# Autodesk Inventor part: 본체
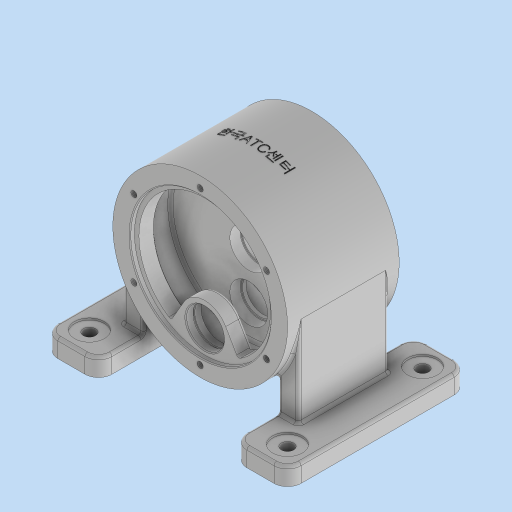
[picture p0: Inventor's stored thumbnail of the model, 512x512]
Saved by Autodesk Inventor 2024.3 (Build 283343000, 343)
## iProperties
Created: 2025-12
Part Number: 본체
Material: 일반
Document SubType Name: Modeling
Designer: PC2-02
Density: 1 g/cm^3
Appearance: 기본값
Author: PC2-02
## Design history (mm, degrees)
sketch "스케치1"
  geometry: L1 (-135, 100)-(135, 100); L2 (135, 100)-(135, -100); L3 (135, -100)-(-135, -100); L4 (-135, -100)-(-135, 100); 1 further point
  constraints: 8 end point, 2 parallel, 1 horizontal, 1 perpendicular
  dimensions: "d0" = 270 distance between parallel lines of L2 L4; "d1" = 135 distance from line of point (0, 0) L4; "d2" = 200 distance between parallel lines of L3 L1; "d3" = 100 distance from line of L3 point (0, 0)
extrude "돌출1" new body sketch "스케치1" distance "d4" = 20; taper "d5" = 0 deg
sketch "스케치2"
  geometry: L1 (135, 0)-(-135, 0) reference; C1 r 97 at (0, 120); 2 further points
  constraints: 1 centre point, 1 midpoint, 1 vertical alignment
  dimensions: "d6" = 194 diameter of C1; "d7" = 120 distance from line of L1 C1.centre
extrude "돌출2" join sketch "스케치2" stored distance "d8" = 124; taper "d9" = 0 deg
sketch "스케치3"
  geometry: L1 (0, 20)-(270, 20) reference; L2 (0, 0)-(270, 0) reference; L3 (60, 20)-(210, 20); L4 (210, 20)-(210, 0); L5 (210, 0)-(60, 0); L6 (60, 0)-(60, 20); L7 (0, 0)-(0, 20) reference; L8 (270, 0)-(270, 20) reference; 3 further points
  constraints: 8 end point, 2 parallel, 2 point on line, 1 horizontal, 1 perpendicular
  dimensions: "d10" = 60 distance between parallel lines of L7 L6; "d11" = 60 distance between parallel lines of L8 L4
extrude "돌출3" cut sketch "스케치3" extent not by distance; stored distance "d12" = 0; taper "d13" = 0 deg
sketch "스케치4"
  geometry: L1 (75, 50)-(97, 50); L2 (97, 50)-(97, -50); L3 (97, -50)-(75, -50); L4 (75, -100)-(75, 100) reference; L5 (75, -50)-(75, 50); L6 (-75, 100)-(-75, -100) reference; L7 (-75, 50)-(-97, 50); L8 (-97, 50)-(-97, -50); L9 (-97, -50)-(-75, -50); L10 (-75, -50)-(-75, 50); 2 further points
  constraints: 16 end point, 3 parallel, 3 point on line, 2 horizontal, 2 perpendicular, 1 collinear
  dimensions: "d14" = 100 distance between parallel lines of L3 L1; "d15" = 50 distance from line of L3 point (0, 0); "d16" = 22 distance between parallel lines of L2 L4; "d17" = 100 distance between parallel lines of L9 L7; "d18" = 50 distance from line of point (0, 0) L7; "d19" = 22 distance between parallel lines of L6 L8
extrude "돌출4" join sketch "스케치4" stored distance "d20" = 10; taper "d21" = 0 deg
sketch "스케치5"
  geometry: L1 (75, 20)-(75, 0) reference; L2 (75, 8)-(36.6, 30.17); L3 (75, 20)-(75, 58.486) reference; L4 (75, 0)-(135, 0) reference; L5 (-36.6, 30.17)-(-75, 8); L6 (-135, 0)-(-75, 0) reference; L7 (-75, 20)-(-75, 58.486) reference; L8 (-75, 0)-(-75, 20) reference; A1 r 97 centre (0, 120) between (36.6, 30.17) and (75, 58.486) reference; 2 further points
  constraints: 4 end point, 2 point on circle, 2 point on line
  dimensions: "d22" = 60 deg angle of L2 L3; "d23" = 8 distance from line of L4 L2.start; "d24" = 8 distance from line of L6 L5.end; "d25" = 60 deg angle of L7 L5
extrude "돌출5" join sketch "스케치5" stored distance "d26" = 12; taper "d27" = 0 deg
sketch "스케치6"
  geometry: C1 r 97 at (0, 0) reference; 2 further points
  constraints: 1 coincident
hole "구멍1" sketch "스케치6" at (0, 0) diameter "d28" = 146; stored, may be unused: countersink angle "d32" = 90 deg, drill point angle "d34" = 0 deg; dims "d29" = 6, "d30" = 156, "d31" = 5, "d33" = 17
sketch "스케치7"
  geometry: C1 r 97 at (0, 0) reference; 2 further points
  constraints: 1 coincident
hole "구멍2" sketch "스케치7" at (0, 0) diameter "d35" = 42; stored, may be unused: countersink angle "d39" = 90 deg, drill point angle "d41" = 0 deg; dims "d36" = 6, "d37" = 174, "d38" = 32, "d40" = 12
sketch "스케치8"
  geometry: C1 r 97 at (0, 0) reference; 2 further points
  constraints: 1 coincident
hole "구멍3" sketch "스케치8" at (0, 0) diameter "d42" = 146; stored, may be unused: countersink angle "d46" = 90 deg, drill point angle "d48" = 0 deg; dims "d43" = 6, "d44" = 156, "d45" = 5, "d47" = 17
sketch "스케치9"
  geometry: C1 r 97 at (0, 0) reference; 2 further points
  constraints: 1 coincident
hole "구멍4" sketch "스케치9" at (0, 0) diameter "d49" = 174; stored, may be unused: countersink angle "d53" = 90 deg, drill point angle "d55" = 0 deg; dims "d50" = 6, "d51" = 4, "d52" = 2, "d54" = 32
sketch "스케치10"
  geometry: L1 (23.383, -39)-(37.148, -62.842); L2 (-23.383, -39)-(-37.148, -62.842); L3 (0, 0)-(0, -73); C1 r 21 at (0, 0) reference; C2 r 97 at (0, 0) reference; A1 r 27 centre (0, -52.5) between (23.383, -39) and (-23.383, -39); A2 r 73 centre (0, 0) between (-37.148, -62.842) and (37.148, -62.842) reference; 1 further point
  constraints: 6 end point, 5 point on circle, 2 tangent, 1 centre point, 1 vertical, 1 vertical alignment
  dimensions: "d57" = 27 radius of A1; "d58" = 52.5 distance of A1.centre C1.centre; "d59" = 30 deg angle of L1 L3; "d60" = 60 deg angle of L2 L1
extrude "돌출6" join sketch "스케치10" distance "d61" = 17; taper "d62" = 0 deg
sketch "스케치11"
  geometry: A1 r 27 centre (0, -52.5) between (23.383, -39) and (-23.383, -39) reference; 2 further points
  constraints: 1 coincident
hole "구멍5" sketch "스케치11" at (0, -52.5) diameter "d63" = 42; stored, may be unused: countersink angle "d67" = 90 deg, drill point angle "d69" = 0 deg; dims "d64" = 6, "d65" = 4, "d66" = 2, "d68" = 8.05
sketch "스케치12"
  geometry: A1 r 27 centre (0, 0) between (23.383, 13.5) and (-23.383, 13.5) reference; 2 further points
  constraints: 1 coincident
hole "구멍6" sketch "스케치12" at (0, 0) diameter "d70" = 42; stored, may be unused: countersink angle "d74" = 90 deg, drill point angle "d76" = 0 deg; dims "d71" = 6, "d72" = 44.5, "d73" = 1.95, "d75" = 12
sketch "스케치17"
  geometry: A1 r 27 centre (0, -52.5) between (23.383, -39) and (-23.383, -39) reference; 2 further points
  constraints: 1 coincident
hole "구멍11" sketch "스케치17" at (0, -52.5) diameter "d123" = 38; stored, may be unused: countersink angle "d127" = 90 deg, drill point angle "d129" = 0 deg; dims "d124" = 6, "d125" = 42, "d126" = 12, "d128" = 12
sketch "스케치14" dims "d84" = 170
  geometry: C1 r 97 at (0, 0) reference; 3 further points
  constraints: 2 vertical alignment, 3 other
hole "구멍8" sketch "스케치14" at (0, 85) diameter "d85" = 6.647; stored, may be unused: countersink angle "d89" = 90 deg, drill point angle "d91" = 118 deg; dims "d86" = 16, "d87" = 4, "d88" = 2, "d90" = 18
sketch "스케치15"
  geometry: 2 further points
  dimensions: "d95" = 110 horizontal distance of point (0, 0) point (-110, -75); "d96" = 75 vertical distance of point (0, 0) point (-110, -75)
hole "구멍9" sketch "스케치15" at (-110, -75) diameter "d97" = 13.5; stored, may be unused: countersink angle "d101" = 90 deg, drill point angle "d103" = 0 deg; dims "d98" = 6, "d99" = 33, "d100" = 2, "d102" = 17
fillet "모깎기1" dims "d110" = 15
fillet "모깎기3" dims "d112" = 3
fillet "모깎기4" dims "d113" = 3
fillet "모깎기5" dims "d114" = 3
fillet "모깎기6" dims "d115" = 3
sketch "스케치16"
  geometry: C1 r 21 at (0, 0) reference; 2 further points
  constraints: 1 coincident
hole "구멍10" sketch "스케치16" at (0, 0) diameter "d116" = 38; stored, may be unused: countersink angle "d120" = 90 deg, drill point angle "d122" = 0 deg; dims "d117" = 6, "d118" = 4, "d119" = 2, "d121" = 12
fillet "모깎기7" dims "d130" = 0.6
chamfer "모따기1" distance "d131" = 1; stored, may be unused: second distance "d132" = 2, angle "d133" = 45 deg
node "작업 평면1"
sketch "스케치18"
  geometry: L1 (-45, 6.5)-(45, 6.5); L2 (45, 6.5)-(45, -6.5); L3 (45, -6.5)-(-45, -6.5); L4 (-45, -6.5)-(-45, 6.5); L5 (-45, 0)-(45, 0); L6 (0, -6.5)-(0, 6.5); 3 further points
  constraints: 6 midpoint, 4 end point, 2 coincident, 1 vertical, 2 other
  dimensions: "d135" = 13 distance between parallel lines of L3 L1; "d136" = 90 distance between parallel lines of L4 L2
feature "엠보싱1" sketch "스케치18" dims "d137" = 0.5, "d138" = 0
fillet "모깎기8" dims "d144" = 3
fillet "모깎기9" dims "d145" = 3
fillet "모깎기10" dims "d146" = 3
fillet "모깎기11" dims "d147" = 3
fillet "모깎기12" dims "d148" = 3
node "솔리드1"
pattern_circular "원형 패턴1" dims angle "d93" = 360 deg
mirror "미러1"
pattern_linear "직사각형 패턴1" dims "d106" = 220, "d109" = 150
feature "A9D066F2-1C7D-4E18-AEED-F7BC21143FA4" dims "d28" = 146, "d29" = 6, "d30" = 156, "d31" = 5, "d32" = 90 deg, "d33" = 17, "d34" = 0
other parameters: "d134" = 217
